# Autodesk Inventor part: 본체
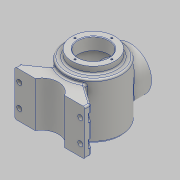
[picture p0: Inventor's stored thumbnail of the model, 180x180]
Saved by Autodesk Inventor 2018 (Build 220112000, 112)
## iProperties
Created: 2021-04
Part Number: 본체
Material: 알루미늄 6061
Document SubType Name: Modeling
Designer: home
Density: 2.7 g/cm^3
Appearance: 알루미늄 - 평지
Mass: 1642.08 g
Surface Area: 1040.59 cm^2
Volume: 608.179 cm^3
Author: home
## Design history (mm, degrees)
sketch "스케치1"
  geometry: L1 (0, 60)-(0, -60); L2 (0, 60)-(27, 60); L3 (38, 60)-(38, 48); L4 (38, 48)-(50, 48); L5 (50, -48.336)-(50, 48); L6 (27, 60)-(27, 38); L7 (27, 60)-(38, 60); L8 (40, -41.916)-(40, 38); L9 (40, 38)-(27, 38); L10 (0, -50)-(0, -60); A1 r 113 centre (0, 53) between (0, -60) and (50, -48.336); A2 r 103 centre (0, 53) between (0, -50) and (40, -41.916); 2 further points
  constraints: 20 end point, 4 perpendicular, 4 point on circle, 3 vertical, 2 centre point, 2 horizontal, 1 coincident, 1 collinear, 1 midpoint, 1 point on line, 1 other
  dimensions: "d0" = 120 distance of L1.start L1.end; "d1" = 38 distance of L1.start L3.start; "d2" = 12 distance of L3.start L3.end; "d5" = 226 diameter of A1; "d6" = 50 distance between parallel lines of L1 L5; "d7" = 22 distance of L2.end L6.end; "d8" = 54 diameter of L6 L1; "d10" = 10 radial gap between concentric circles of A1 A2
revolve "회전1" sketch "스케치1" stored, may be unused: angle "d11" = 90 deg
node "작업 평면3"
  node "작업 평면2"
sketch "스케치4"
  geometry: L1 (-62, -77)-(-25.981, -77); L2 (62, -77)-(62, -67); L3 (62, -67)-(26.694, -42.278); L4 (0, -77)-(0, -62); L5 (-25.981, -77)-(25.981, -77); L6 (25.981, -77)-(62, -77); L7 (-62, -67)-(-26.694, -42.278); L8 (-62, -77)-(-62, -67); A1 r 50 centre (0, 0) between (26.694, -42.278) and (-26.694, -42.278) reference; A2 r 30 centre (0, -92) between (25.981, -77) and (-25.981, -77); A3 r 50 centre (0, 0) between (-26.694, -42.278) and (26.694, -42.278); 3 further points
  constraints: 16 end point, 8 point on circle, 3 horizontal, 3 vertical, 2 centre point, 2 vertical alignment, 1 coincident, 1 concentric, 1 midpoint, 1 point on line
  dimensions: "d23" = 77 distance from line of L1 point (0, 0); "d24" = 10 distance of L2.start L2.end; "d25" = 55 deg angle of L2 L3; "d27" = 60 diameter of A2; "d32" = 77 distance of L4.start point (0, 0); "d33" = 62 distance from line of L4.start L8; "d34" = 124 distance between parallel lines of L2 L8; "d39" = 19.32145 distance from line of point (0, 0) L7; "d41" = 62 distance from line of point (0, -62) L2; "d42" = 55 deg angle of L7 L8; "d43" = 15 distance of L4.end L4.start
extrude "돌출3" join sketch "스케치4" distance "d30" = 80; taper "d31" = 0 deg
sketch "스케치5"
  geometry: L1 (36.019, 0)-(36.019, -80) reference; L2 (0, 0)-(36.019, 0) reference; C1 r 4.5 at (28.019, -20); 1 further point
  constraints: 1 centre point
  dimensions: "d44" = 9 diameter of C1; "d45" = 8 distance from line of L1 C1.centre; "d46" = 20 distance from line of L2 C1.centre
extrude "돌출4" cut sketch "스케치5" distance "d47" = 20; taper "d48" = 0 deg
node "작업 평면5"
sketch "스케치7"
  geometry: L1 (-54, 13)-(-62, 13); L2 (-54, 27)-(-62, 27); L3 (-62, 13)-(-62, 27); C1 r 4.5 at (-54, 20) reference; A1 r 7 centre (-54, 20) between (-54, 13) and (-54, 27); A2 r 7 centre (-54, 20) between (-54, 27) and (-54, 13); 1 further point
  constraints: 6 end point, 4 point on circle, 2 centre point, 2 horizontal, 2 tangent, 1 coincident, 1 vertical
  dimensions: "d54" = 14 diameter of A1; "d55" = 8 distance from line of L3 C1.centre
extrude "돌출6" cut sketch "스케치7" distance "d56" = 20; taper "d57" = 0 deg
sketch "스케치8" dims "d58" = 65
  geometry: 3 further points
  constraints: 2 vertical alignment, 1 coincident, 2 other
hole "구멍1" sketch "스케치8" at (0, 32.5) diameter "d59" = 3.242; stored, may be unused: countersink angle "d63" = 90 deg, drill point angle "d65" = 118 deg; dims "d60" = 8, "d61" = 4, "d62" = 2, "d64" = 10
fillet "모깎기1" dims "d82" = 3
fillet "모깎기2" dims "d83" = 3
fillet "모깎기3" dims "d84" = 3
chamfer "모따기1" distance "d86" = 1; stored, may be unused: second distance "d87" = 2, angle "d88" = 45 deg
fillet "모깎기4" dims "d89" = 3
fillet "모깎기5" dims "d90" = 3
node "작업 평면9"
sketch "스케치12"
  geometry: L1 (-38, 60)-(38, 60) reference; C1 r 38 at (0, -2); 1 further point
  constraints: 1 centre point, 1 vertical alignment
  dimensions: "d92" = 76 diameter of C1; "d93" = 62 distance from line of L1 C1.centre
extrude "돌출7" join sketch "스케치12" stored distance "d94" = 20; taper "d95" = 0 deg
sketch "스케치13"
  geometry: C1 r 38 at (0, 0) reference; C2 r 27 at (0, 0); 1 further point
  constraints: 1 centre point, 1 coincident
  dimensions: "d96" = 54 diameter of C2
extrude "돌출8" cut sketch "스케치13" stored distance "d97" = 20; taper "d98" = 0 deg
sketch "스케치14" dims "d99" = 65
  geometry: C1 r 27 at (0, 0) reference; C2 r 38 at (0, 0) reference; 3 further points
  constraints: 2 horizontal alignment, 1 coincident, 2 other
hole "구멍3" sketch "스케치14" at (-32.5, 0) diameter "d100" = 3.242; stored, may be unused: countersink angle "d104" = 90 deg, drill point angle "d106" = 118 deg; dims "d101" = 8, "d102" = 4, "d103" = 2, "d105" = 10
fillet "모깎기6" dims "d110" = 3
chamfer "모따기2" distance "d111" = 1; stored, may be unused: second distance "d112" = 2, angle "d113" = 45 deg
node "작업 평면12"
sketch "스케치19"
  geometry: 2 further points
  constraints: 2 coincident, 1 other
feature "엠보싱1" sketch "스케치19" dims "d23" = 77, "d24" = 10, "d25" = 55 deg, "d27" = 60, "d32" = 77, "d33" = 62, "d34" = 124, "d39" = 19.32145, "d41" = 62, "d42" = 55 deg, "d43" = 15, "d116" = 0.5, "d117" = 0
node "솔리드1"
mirror "미러1"
mirror "미러2"
pattern_circular "원형 패턴1" dims angle "d67" = 360 deg
pattern_circular "원형 패턴3" dims angle "d108" = 360 deg
node "투영된 루프1"
node "투영된 루프3"
node "투영된 루프4"
other parameters: "d53" = -71, "d91" = 65
